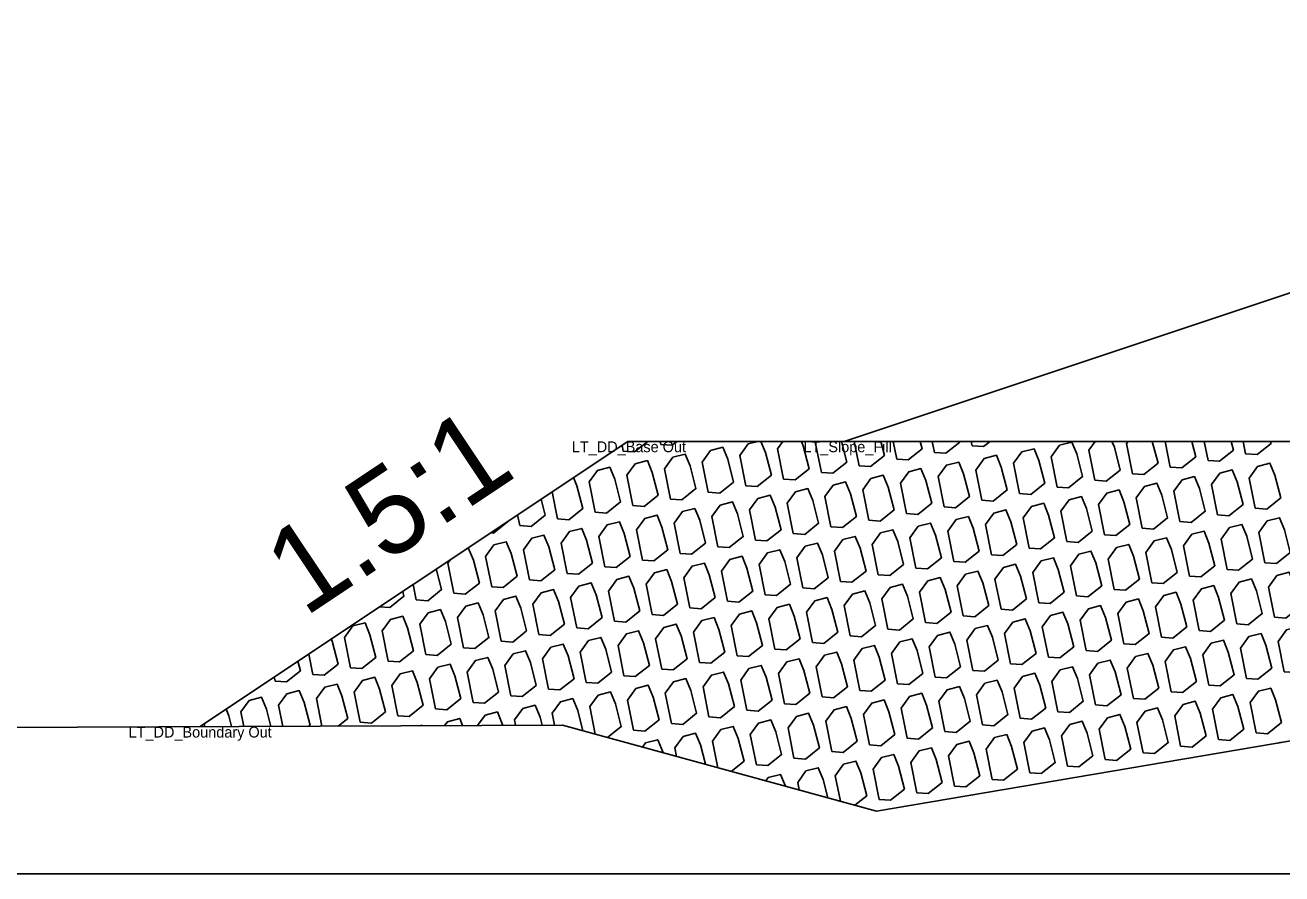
# Model space of a CAD drawing. Extents: x -26 to 203, y -10 to 20020.
# Drawn here: x 60.88 to 72.5, y 17500 to 17507.85 of the extents above; entities that cross this region are included whole.
import ezdxf

# ---------------------------------------------------------------- set-up
doc = ezdxf.new("R2010")
doc.units = 0
for name, color, linetype in [('Default', 7, 'Continuous'), ('Exist Cross Section Cell', 7, 'Continuous'), ('Exist XS Ground Line', 7, 'Continuous'), ('Old_Level_1', 7, 'Continuous'), ('Prop CMT Rip Rap Class II', 7, 'Continuous'), ('Prop CMT Slope Grass', 7, 'Continuous'), ('Prop XS Side Slope Text', 7, 'Continuous')]:
    doc.layers.add(name, color=color, linetype=linetype)

msp = doc.modelspace()

# ---------------------------------------------------------------- linework, layer by layer
at = {"layer": 'Exist Cross Section Cell'}
msp.add_line((0, 17500), (100, 17500), dxfattribs=at)
at = {"layer": 'Exist XS Ground Line'}
for p, q in [((59.91, 17501.349), (65.847, 17501.376)), ((65.847, 17501.376), (68.75, 17500.58)), ((68.75, 17500.58), (73.775, 17501.433))]:
    msp.add_line(p, q, dxfattribs=at)
at = {"layer": 'Old_Level_1'}
for p, q in [((66.397, 17503.965), (66.408, 17503.91)), ((66.751, 17504), (66.757, 17503.972)), ((68.544, 17504), (68.589, 17503.775)), ((68.905, 17504), (68.937, 17503.836)), ((69.266, 17504), (69.286, 17503.898)), ((69.626, 17504), (69.634, 17503.959)), ((71.419, 17504), (71.466, 17503.762)), ((71.78, 17504), (71.815, 17503.824)), ((72.141, 17504), (72.163, 17503.885)), ((65.75, 17503.534), (65.8, 17503.283)), ((65.431, 17503.321), (65.451, 17503.222)), ((64.466, 17502.677), (64.494, 17502.533)), ((63.5, 17502.033), (63.537, 17501.845)), ((63.181, 17501.821), (63.189, 17501.783)), ((62.534, 17501.39), (62.54, 17501.361))]:
    msp.add_line(p, q, dxfattribs=at)
for points in [[(66.408, 17503.91), (66.513, 17503.902), (66.636, 17504)], [(66.757, 17503.972), (66.862, 17503.964), (66.907, 17504)], [(67.654, 17504), (67.564, 17503.977), (67.487, 17503.87), (67.543, 17503.59)], [(67.543, 17503.59), (67.648, 17503.583), (67.778, 17503.686), (67.723, 17503.897), (67.681, 17504)], [(67.885, 17504), (67.836, 17503.932), (67.891, 17503.652)], [(67.891, 17503.652), (67.997, 17503.644), (68.126, 17503.747), (68.072, 17503.958), (68.055, 17504)], [(68.189, 17504), (68.184, 17503.993), (68.24, 17503.713)], [(68.24, 17503.713), (68.345, 17503.706), (68.475, 17503.809), (68.425, 17504)], [(68.589, 17503.775), (68.694, 17503.767), (68.823, 17503.87), (68.79, 17504)], [(68.937, 17503.836), (69.043, 17503.829), (69.172, 17503.932), (69.154, 17504)], [(69.286, 17503.898), (69.391, 17503.89), (69.521, 17503.993), (69.519, 17504)], [(69.634, 17503.959), (69.74, 17503.952), (69.801, 17504)], [(70.072, 17503.517), (70.177, 17503.509), (70.307, 17503.612), (70.252, 17503.823), (70.207, 17503.932), (70.093, 17503.903), (70.016, 17503.797), (70.072, 17503.517)], [(70.421, 17503.578), (70.526, 17503.57), (70.655, 17503.674), (70.601, 17503.884), (70.556, 17503.994), (70.442, 17503.964), (70.365, 17503.858), (70.421, 17503.578)], [(70.772, 17504), (70.714, 17503.92), (70.769, 17503.64)], [(70.769, 17503.64), (70.874, 17503.632), (71.004, 17503.735), (70.949, 17503.946), (70.927, 17504)], [(71.076, 17504), (71.062, 17503.981), (71.118, 17503.701)], [(71.118, 17503.701), (71.223, 17503.693), (71.353, 17503.797), (71.3, 17504)], [(71.466, 17503.762), (71.572, 17503.755), (71.701, 17503.858), (71.664, 17504)], [(71.815, 17503.824), (71.92, 17503.816), (72.05, 17503.919), (72.029, 17504)], [(72.163, 17503.885), (72.269, 17503.878), (72.398, 17503.981), (72.393, 17504)], [(69.723, 17503.455), (69.829, 17503.447), (69.958, 17503.551), (69.904, 17503.761), (69.859, 17503.871), (69.745, 17503.842), (69.668, 17503.735), (69.723, 17503.455)], [(71.555, 17503.258), (71.66, 17503.251), (71.79, 17503.354), (71.736, 17503.565), (71.69, 17503.674), (71.577, 17503.645), (71.5, 17503.538), (71.555, 17503.258)], [(71.904, 17503.32), (72.009, 17503.312), (72.139, 17503.415), (72.084, 17503.626), (72.039, 17503.736), (71.925, 17503.706), (71.848, 17503.6), (71.904, 17503.32)], [(65.8, 17503.283), (65.905, 17503.275), (66.035, 17503.379), (65.98, 17503.589), (65.949, 17503.666)], [(71.207, 17503.197), (71.312, 17503.189), (71.441, 17503.292), (71.387, 17503.503), (71.342, 17503.613), (71.228, 17503.583), (71.151, 17503.477), (71.207, 17503.197)], [(65.451, 17503.222), (65.557, 17503.214), (65.686, 17503.317), (65.648, 17503.465)], [(67.632, 17503.086), (67.737, 17503.079), (67.867, 17503.182), (67.812, 17503.392), (67.767, 17503.502), (67.653, 17503.473), (67.576, 17503.366), (67.632, 17503.086)], [(65.181, 17503.154), (65.208, 17503.152), (65.337, 17503.256), (65.337, 17503.258)], [(64.843, 17502.595), (64.948, 17502.587), (65.078, 17502.69), (65.023, 17502.901), (64.978, 17503.01), (64.957, 17503.005)], [(64.811, 17502.908), (64.787, 17502.875), (64.843, 17502.595)], [(67.023, 17502.459), (67.129, 17502.452), (67.258, 17502.555), (67.204, 17502.765), (67.159, 17502.875), (67.045, 17502.846), (66.968, 17502.739), (67.023, 17502.459)], [(64.494, 17502.533), (64.6, 17502.525), (64.729, 17502.629), (64.68, 17502.82)], [(64.156, 17502.471), (64.251, 17502.464), (64.381, 17502.567), (64.369, 17502.613)], [(63.886, 17501.906), (63.991, 17501.898), (64.121, 17502.002), (64.066, 17502.212), (64.021, 17502.322), (63.908, 17502.293), (63.83, 17502.186), (63.886, 17501.906)], [(63.537, 17501.845), (63.643, 17501.837), (63.772, 17501.94), (63.718, 17502.151), (63.709, 17502.173)], [(66.415, 17501.832), (66.52, 17501.825), (66.65, 17501.928), (66.595, 17502.138), (66.55, 17502.248), (66.437, 17502.219), (66.36, 17502.112), (66.415, 17501.832)], [(63.189, 17501.783), (63.294, 17501.776), (63.424, 17501.879), (63.401, 17501.967)], [(64.672, 17501.525), (64.777, 17501.517), (64.907, 17501.621), (64.852, 17501.831), (64.807, 17501.941), (64.694, 17501.911), (64.617, 17501.805), (64.672, 17501.525)], [(65.021, 17501.586), (65.126, 17501.579), (65.256, 17501.682), (65.201, 17501.893), (65.156, 17502.002), (65.042, 17501.973), (64.965, 17501.866), (65.021, 17501.586)], [(64.324, 17501.463), (64.429, 17501.456), (64.558, 17501.559), (64.504, 17501.77), (64.459, 17501.879), (64.345, 17501.85), (64.268, 17501.743), (64.324, 17501.463)], [(63.501, 17501.365), (63.513, 17501.375), (63.458, 17501.585), (63.413, 17501.695), (63.299, 17501.666), (63.222, 17501.559), (63.261, 17501.364)], [(63.774, 17501.366), (63.861, 17501.436), (63.807, 17501.647), (63.762, 17501.756), (63.648, 17501.727), (63.571, 17501.621), (63.621, 17501.366)], [(66.504, 17501.328), (66.609, 17501.321), (66.739, 17501.424), (66.684, 17501.634), (66.639, 17501.744), (66.525, 17501.715), (66.448, 17501.608), (66.504, 17501.328)], [(69.382, 17501.316), (69.487, 17501.308), (69.616, 17501.411), (69.562, 17501.622), (69.517, 17501.732), (69.403, 17501.702), (69.326, 17501.596), (69.382, 17501.316)], [(69.73, 17501.377), (69.836, 17501.37), (69.965, 17501.473), (69.911, 17501.684), (69.865, 17501.793), (69.752, 17501.764), (69.675, 17501.657), (69.73, 17501.377)], [(72.259, 17501.304), (72.365, 17501.296), (72.494, 17501.399), (72.44, 17501.61), (72.395, 17501.719), (72.281, 17501.69), (72.204, 17501.584), (72.259, 17501.304)], [(63.151, 17501.364), (63.11, 17501.524), (63.064, 17501.633), (62.951, 17501.604), (62.874, 17501.498), (62.9, 17501.362)], [(66.036, 17501.324), (65.987, 17501.511), (65.942, 17501.621), (65.828, 17501.592), (65.751, 17501.485), (65.773, 17501.376)], [(66.264, 17501.262), (66.39, 17501.362), (66.336, 17501.573), (66.291, 17501.683), (66.177, 17501.653), (66.1, 17501.547), (66.15, 17501.293)], [(68.684, 17501.193), (68.79, 17501.185), (68.919, 17501.289), (68.865, 17501.499), (68.82, 17501.609), (68.706, 17501.579), (68.629, 17501.473), (68.684, 17501.193)], [(69.033, 17501.254), (69.138, 17501.247), (69.268, 17501.35), (69.213, 17501.561), (69.168, 17501.67), (69.055, 17501.641), (68.977, 17501.534), (69.033, 17501.254)], [(71.562, 17501.181), (71.667, 17501.173), (71.797, 17501.276), (71.742, 17501.487), (71.697, 17501.596), (71.584, 17501.567), (71.507, 17501.461), (71.562, 17501.181)], [(71.911, 17501.242), (72.016, 17501.234), (72.146, 17501.338), (72.091, 17501.548), (72.046, 17501.658), (71.932, 17501.629), (71.855, 17501.522), (71.911, 17501.242)], [(62.787, 17501.362), (62.761, 17501.462), (62.736, 17501.524)], [(65.294, 17501.373), (65.29, 17501.389), (65.245, 17501.498), (65.131, 17501.469), (65.061, 17501.372)], [(65.658, 17501.375), (65.639, 17501.45), (65.593, 17501.56), (65.48, 17501.53), (65.403, 17501.424), (65.413, 17501.374)], [(67.987, 17501.07), (68.093, 17501.062), (68.222, 17501.166), (68.168, 17501.376), (68.122, 17501.486), (68.009, 17501.456), (67.932, 17501.35), (67.987, 17501.07)], [(68.336, 17501.131), (68.441, 17501.124), (68.571, 17501.227), (68.516, 17501.438), (68.471, 17501.547), (68.357, 17501.518), (68.28, 17501.411), (68.336, 17501.131)], [(70.865, 17501.058), (70.97, 17501.05), (71.1, 17501.153), (71.045, 17501.364), (71, 17501.474), (70.886, 17501.444), (70.809, 17501.338), (70.865, 17501.058)], [(71.214, 17501.119), (71.319, 17501.112), (71.448, 17501.215), (71.394, 17501.425), (71.349, 17501.535), (71.235, 17501.506), (71.158, 17501.399), (71.214, 17501.119)], [(64.55, 17501.37), (64.548, 17501.375), (64.527, 17501.37)], [(64.923, 17501.372), (64.896, 17501.437), (64.782, 17501.407), (64.756, 17501.371)], [(67.407, 17500.948), (67.525, 17501.043), (67.47, 17501.253), (67.425, 17501.363), (67.312, 17501.334), (67.234, 17501.227), (67.283, 17500.982)], [(67.639, 17501.009), (67.744, 17501.001), (67.873, 17501.104), (67.819, 17501.315), (67.774, 17501.424), (67.66, 17501.395), (67.583, 17501.289), (67.639, 17501.009)], [(70.516, 17500.996), (70.622, 17500.989), (70.751, 17501.092), (70.697, 17501.302), (70.652, 17501.412), (70.538, 17501.383), (70.461, 17501.276), (70.516, 17500.996)], [(66.776, 17501.121), (66.773, 17501.13), (66.728, 17501.24), (66.614, 17501.211), (66.587, 17501.173)], [(67.168, 17501.014), (67.122, 17501.192), (67.077, 17501.301), (66.963, 17501.272), (66.886, 17501.166), (66.902, 17501.087)], [(72.484, 17501.214), (72.483, 17501.215), (72.462, 17501.21)], [(68.549, 17500.635), (68.66, 17500.723), (68.605, 17500.934), (68.56, 17501.043), (68.446, 17501.014), (68.369, 17500.907), (68.416, 17500.672)], [(67.908, 17500.811), (67.863, 17500.92), (67.749, 17500.891), (67.727, 17500.861)], [(68.3, 17500.704), (68.257, 17500.872), (68.211, 17500.982), (68.098, 17500.952), (68.021, 17500.846), (68.034, 17500.776)]]:
    msp.add_lwpolyline(points, dxfattribs=at)
for points in [[(67.194, 17503.529), (67.3, 17503.521), (67.429, 17503.624), (67.375, 17503.835), (67.329, 17503.945), (67.216, 17503.915), (67.139, 17503.809)], [(66.497, 17503.406), (66.602, 17503.398), (66.732, 17503.502), (66.677, 17503.712), (66.632, 17503.822), (66.519, 17503.792), (66.441, 17503.686)], [(66.846, 17503.467), (66.951, 17503.46), (67.08, 17503.563), (67.026, 17503.774), (66.981, 17503.883), (66.867, 17503.854), (66.79, 17503.747)], [(69.375, 17503.394), (69.48, 17503.386), (69.61, 17503.489), (69.555, 17503.7), (69.51, 17503.809), (69.396, 17503.78), (69.319, 17503.674)], [(72.252, 17503.381), (72.358, 17503.374), (72.487, 17503.477), (72.433, 17503.687), (72.388, 17503.797), (72.274, 17503.768), (72.197, 17503.661)], [(66.148, 17503.345), (66.254, 17503.337), (66.383, 17503.44), (66.329, 17503.651), (66.284, 17503.76), (66.17, 17503.731), (66.093, 17503.625)], [(68.678, 17503.271), (68.783, 17503.263), (68.912, 17503.366), (68.858, 17503.577), (68.813, 17503.687), (68.699, 17503.657), (68.622, 17503.551)], [(69.026, 17503.332), (69.131, 17503.325), (69.261, 17503.428), (69.206, 17503.638), (69.161, 17503.748), (69.048, 17503.719), (68.971, 17503.612)], [(67.98, 17503.148), (68.086, 17503.14), (68.215, 17503.243), (68.161, 17503.454), (68.116, 17503.564), (68.002, 17503.534), (67.925, 17503.428)], [(68.329, 17503.209), (68.434, 17503.202), (68.564, 17503.305), (68.509, 17503.515), (68.464, 17503.625), (68.35, 17503.596), (68.273, 17503.489)], [(70.858, 17503.135), (70.963, 17503.128), (71.093, 17503.231), (71.038, 17503.442), (70.993, 17503.551), (70.879, 17503.522), (70.802, 17503.415)], [(67.283, 17503.025), (67.388, 17503.017), (67.518, 17503.12), (67.464, 17503.331), (67.418, 17503.441), (67.305, 17503.411), (67.228, 17503.305)], [(70.509, 17503.074), (70.615, 17503.066), (70.744, 17503.17), (70.69, 17503.38), (70.645, 17503.49), (70.531, 17503.46), (70.454, 17503.354)], [(66.935, 17502.963), (67.04, 17502.956), (67.169, 17503.059), (67.115, 17503.27), (67.07, 17503.379), (66.956, 17503.35), (66.879, 17503.243)], [(69.812, 17502.951), (69.917, 17502.943), (70.047, 17503.047), (69.993, 17503.257), (69.947, 17503.367), (69.834, 17503.337), (69.757, 17503.231)], [(70.161, 17503.013), (70.266, 17503.005), (70.396, 17503.108), (70.341, 17503.319), (70.296, 17503.428), (70.182, 17503.399), (70.105, 17503.293)], [(66.237, 17502.84), (66.343, 17502.833), (66.472, 17502.936), (66.418, 17503.147), (66.373, 17503.256), (66.259, 17503.227), (66.182, 17503.12)], [(66.586, 17502.902), (66.691, 17502.894), (66.821, 17502.997), (66.766, 17503.208), (66.721, 17503.318), (66.607, 17503.288), (66.53, 17503.182)], [(69.115, 17502.828), (69.22, 17502.82), (69.35, 17502.924), (69.295, 17503.134), (69.25, 17503.244), (69.136, 17503.215), (69.059, 17503.108)], [(69.464, 17502.89), (69.569, 17502.882), (69.698, 17502.985), (69.644, 17503.196), (69.599, 17503.305), (69.485, 17503.276), (69.408, 17503.17)], [(71.993, 17502.816), (72.098, 17502.808), (72.227, 17502.911), (72.173, 17503.122), (72.128, 17503.232), (72.014, 17503.202), (71.937, 17503.096)], [(72.341, 17502.877), (72.447, 17502.87), (72.576, 17502.973), (72.522, 17503.183), (72.476, 17503.293), (72.363, 17503.264), (72.286, 17503.157)], [(65.54, 17502.718), (65.645, 17502.71), (65.775, 17502.813), (65.721, 17503.024), (65.675, 17503.133), (65.562, 17503.104), (65.485, 17502.997)], [(65.889, 17502.779), (65.994, 17502.771), (66.124, 17502.875), (66.069, 17503.085), (66.024, 17503.195), (65.91, 17503.165), (65.833, 17503.059)], [(68.418, 17502.705), (68.523, 17502.698), (68.653, 17502.801), (68.598, 17503.011), (68.553, 17503.121), (68.439, 17503.092), (68.362, 17502.985)], [(68.766, 17502.767), (68.872, 17502.759), (69.001, 17502.862), (68.947, 17503.073), (68.902, 17503.182), (68.788, 17503.153), (68.711, 17503.047)], [(71.295, 17502.693), (71.401, 17502.685), (71.53, 17502.788), (71.476, 17502.999), (71.431, 17503.109), (71.317, 17503.079), (71.24, 17502.973)], [(71.644, 17502.754), (71.749, 17502.747), (71.879, 17502.85), (71.824, 17503.06), (71.779, 17503.17), (71.666, 17503.141), (71.588, 17503.034)], [(65.192, 17502.656), (65.297, 17502.648), (65.426, 17502.752), (65.372, 17502.962), (65.327, 17503.072), (65.213, 17503.042), (65.136, 17502.936)], [(67.721, 17502.582), (67.826, 17502.575), (67.955, 17502.678), (67.901, 17502.888), (67.856, 17502.998), (67.742, 17502.969), (67.665, 17502.862)], [(68.069, 17502.644), (68.174, 17502.636), (68.304, 17502.739), (68.25, 17502.95), (68.204, 17503.06), (68.091, 17503.03), (68.014, 17502.924)], [(70.598, 17502.57), (70.704, 17502.562), (70.833, 17502.665), (70.779, 17502.876), (70.733, 17502.986), (70.62, 17502.956), (70.543, 17502.85)], [(70.947, 17502.631), (71.052, 17502.624), (71.182, 17502.727), (71.127, 17502.938), (71.082, 17503.047), (70.968, 17503.018), (70.891, 17502.911)], [(67.372, 17502.521), (67.477, 17502.513), (67.607, 17502.616), (67.552, 17502.827), (67.507, 17502.937), (67.393, 17502.907), (67.316, 17502.801)], [(69.901, 17502.447), (70.006, 17502.439), (70.136, 17502.543), (70.081, 17502.753), (70.036, 17502.863), (69.923, 17502.833), (69.845, 17502.727)], [(70.25, 17502.508), (70.355, 17502.501), (70.484, 17502.604), (70.43, 17502.815), (70.385, 17502.924), (70.271, 17502.895), (70.194, 17502.788)], [(66.326, 17502.336), (66.432, 17502.329), (66.561, 17502.432), (66.507, 17502.643), (66.461, 17502.752), (66.348, 17502.723), (66.271, 17502.616)], [(66.675, 17502.398), (66.78, 17502.39), (66.91, 17502.493), (66.855, 17502.704), (66.81, 17502.814), (66.696, 17502.784), (66.619, 17502.678)], [(69.204, 17502.324), (69.309, 17502.316), (69.439, 17502.42), (69.384, 17502.63), (69.339, 17502.74), (69.225, 17502.71), (69.148, 17502.604)], [(69.552, 17502.386), (69.658, 17502.378), (69.787, 17502.481), (69.733, 17502.692), (69.688, 17502.801), (69.574, 17502.772), (69.497, 17502.665)], [(72.43, 17502.373), (72.535, 17502.366), (72.665, 17502.469), (72.611, 17502.679), (72.565, 17502.789), (72.452, 17502.76), (72.375, 17502.653)], [(65.629, 17502.213), (65.734, 17502.206), (65.864, 17502.309), (65.809, 17502.52), (65.764, 17502.629), (65.65, 17502.6), (65.573, 17502.493)], [(65.978, 17502.275), (66.083, 17502.267), (66.212, 17502.37), (66.158, 17502.581), (66.113, 17502.691), (65.999, 17502.661), (65.922, 17502.555)], [(68.855, 17502.263), (68.961, 17502.255), (69.09, 17502.358), (69.036, 17502.569), (68.991, 17502.678), (68.877, 17502.649), (68.8, 17502.543)], [(71.733, 17502.25), (71.838, 17502.243), (71.968, 17502.346), (71.913, 17502.556), (71.868, 17502.666), (71.754, 17502.637), (71.677, 17502.53)], [(72.082, 17502.312), (72.187, 17502.304), (72.316, 17502.407), (72.262, 17502.618), (72.217, 17502.728), (72.103, 17502.698), (72.026, 17502.592)], [(64.932, 17502.091), (65.037, 17502.083), (65.167, 17502.186), (65.112, 17502.397), (65.067, 17502.506), (64.953, 17502.477), (64.876, 17502.37)], [(65.28, 17502.152), (65.386, 17502.144), (65.515, 17502.248), (65.461, 17502.458), (65.416, 17502.568), (65.302, 17502.538), (65.225, 17502.432)], [(68.158, 17502.14), (68.263, 17502.132), (68.393, 17502.235), (68.338, 17502.446), (68.293, 17502.555), (68.18, 17502.526), (68.102, 17502.42)], [(68.507, 17502.201), (68.612, 17502.193), (68.742, 17502.297), (68.687, 17502.507), (68.642, 17502.617), (68.528, 17502.588), (68.451, 17502.481)], [(71.036, 17502.127), (71.141, 17502.12), (71.271, 17502.223), (71.216, 17502.433), (71.171, 17502.543), (71.057, 17502.514), (70.98, 17502.407)], [(71.384, 17502.189), (71.49, 17502.181), (71.619, 17502.284), (71.565, 17502.495), (71.52, 17502.605), (71.406, 17502.575), (71.329, 17502.469)], [(64.583, 17502.029), (64.689, 17502.021), (64.818, 17502.125), (64.764, 17502.335), (64.718, 17502.445), (64.605, 17502.415), (64.528, 17502.309)], [(67.461, 17502.017), (67.566, 17502.009), (67.696, 17502.112), (67.641, 17502.323), (67.596, 17502.433), (67.482, 17502.403), (67.405, 17502.297)], [(67.81, 17502.078), (67.915, 17502.071), (68.044, 17502.174), (67.99, 17502.384), (67.945, 17502.494), (67.831, 17502.465), (67.754, 17502.358)], [(70.339, 17502.004), (70.444, 17501.997), (70.573, 17502.1), (70.519, 17502.311), (70.474, 17502.42), (70.36, 17502.391), (70.283, 17502.284)], [(70.687, 17502.066), (70.792, 17502.058), (70.922, 17502.161), (70.868, 17502.372), (70.822, 17502.482), (70.709, 17502.452), (70.632, 17502.346)], [(64.235, 17501.968), (64.34, 17501.96), (64.469, 17502.063), (64.415, 17502.274), (64.37, 17502.383), (64.256, 17502.354), (64.179, 17502.248)], [(66.764, 17501.894), (66.869, 17501.886), (66.999, 17501.989), (66.944, 17502.2), (66.899, 17502.31), (66.785, 17502.28), (66.708, 17502.174)], [(67.112, 17501.955), (67.218, 17501.948), (67.347, 17502.051), (67.293, 17502.261), (67.248, 17502.371), (67.134, 17502.342), (67.057, 17502.235)], [(69.641, 17501.881), (69.747, 17501.874), (69.876, 17501.977), (69.822, 17502.188), (69.777, 17502.297), (69.663, 17502.268), (69.586, 17502.161)], [(69.99, 17501.943), (70.095, 17501.935), (70.225, 17502.038), (70.17, 17502.249), (70.125, 17502.359), (70.011, 17502.329), (69.934, 17502.223)], [(72.519, 17501.869), (72.624, 17501.861), (72.754, 17501.965), (72.699, 17502.175), (72.654, 17502.285), (72.54, 17502.256), (72.463, 17502.149)], [(66.067, 17501.771), (66.172, 17501.763), (66.301, 17501.866), (66.247, 17502.077), (66.202, 17502.187), (66.088, 17502.157), (66.011, 17502.051)], [(68.944, 17501.759), (69.049, 17501.751), (69.179, 17501.854), (69.125, 17502.065), (69.079, 17502.174), (68.966, 17502.145), (68.889, 17502.038)], [(69.293, 17501.82), (69.398, 17501.812), (69.528, 17501.916), (69.473, 17502.126), (69.428, 17502.236), (69.314, 17502.206), (69.237, 17502.1)], [(71.822, 17501.746), (71.927, 17501.739), (72.057, 17501.842), (72.002, 17502.052), (71.957, 17502.162), (71.843, 17502.133), (71.766, 17502.026)], [(72.17, 17501.808), (72.276, 17501.8), (72.405, 17501.903), (72.351, 17502.114), (72.306, 17502.223), (72.192, 17502.194), (72.115, 17502.088)], [(65.369, 17501.648), (65.475, 17501.64), (65.604, 17501.743), (65.55, 17501.954), (65.505, 17502.064), (65.391, 17502.034), (65.314, 17501.928)], [(65.718, 17501.709), (65.823, 17501.702), (65.953, 17501.805), (65.898, 17502.016), (65.853, 17502.125), (65.739, 17502.096), (65.662, 17501.989)], [(68.247, 17501.636), (68.352, 17501.628), (68.482, 17501.731), (68.427, 17501.942), (68.382, 17502.051), (68.268, 17502.022), (68.191, 17501.916)], [(68.596, 17501.697), (68.701, 17501.689), (68.83, 17501.793), (68.776, 17502.003), (68.731, 17502.113), (68.617, 17502.083), (68.54, 17501.977)], [(71.473, 17501.685), (71.578, 17501.677), (71.708, 17501.78), (71.654, 17501.991), (71.608, 17502.101), (71.495, 17502.071), (71.418, 17501.965)], [(67.55, 17501.513), (67.655, 17501.505), (67.785, 17501.608), (67.73, 17501.819), (67.685, 17501.928), (67.571, 17501.899), (67.494, 17501.793)], [(67.898, 17501.574), (68.004, 17501.566), (68.133, 17501.67), (68.079, 17501.88), (68.034, 17501.99), (67.92, 17501.961), (67.843, 17501.854)], [(70.776, 17501.562), (70.881, 17501.554), (71.011, 17501.657), (70.956, 17501.868), (70.911, 17501.978), (70.797, 17501.948), (70.72, 17501.842)], [(71.125, 17501.623), (71.23, 17501.616), (71.359, 17501.719), (71.305, 17501.929), (71.26, 17502.039), (71.146, 17502.01), (71.069, 17501.903)], [(63.975, 17501.402), (64.08, 17501.394), (64.21, 17501.498), (64.155, 17501.708), (64.11, 17501.818), (63.996, 17501.788), (63.919, 17501.682)], [(67.201, 17501.451), (67.306, 17501.444), (67.436, 17501.547), (67.382, 17501.757), (67.336, 17501.867), (67.223, 17501.838), (67.146, 17501.731)], [(70.079, 17501.439), (70.184, 17501.431), (70.314, 17501.534), (70.259, 17501.745), (70.214, 17501.855), (70.1, 17501.825), (70.023, 17501.719)], [(70.427, 17501.5), (70.533, 17501.493), (70.662, 17501.596), (70.608, 17501.806), (70.563, 17501.916), (70.449, 17501.887), (70.372, 17501.78)], [(66.853, 17501.39), (66.958, 17501.382), (67.087, 17501.485), (67.033, 17501.696), (66.988, 17501.806), (66.874, 17501.776), (66.797, 17501.67)], [(70.168, 17500.935), (70.273, 17500.927), (70.403, 17501.03), (70.348, 17501.241), (70.303, 17501.351), (70.189, 17501.321), (70.112, 17501.215)], [(69.471, 17500.812), (69.576, 17500.804), (69.705, 17500.907), (69.651, 17501.118), (69.606, 17501.228), (69.492, 17501.198), (69.415, 17501.092)], [(69.819, 17500.873), (69.924, 17500.866), (70.054, 17500.969), (69.999, 17501.179), (69.954, 17501.289), (69.841, 17501.26), (69.764, 17501.153)], [(69.122, 17500.75), (69.227, 17500.743), (69.357, 17500.846), (69.302, 17501.057), (69.257, 17501.166), (69.143, 17501.137), (69.066, 17501.03)], [(68.773, 17500.689), (68.879, 17500.681), (69.008, 17500.784), (68.954, 17500.995), (68.909, 17501.105), (68.795, 17501.075), (68.718, 17500.969)]]:
    msp.add_lwpolyline(points, close=True, dxfattribs=at)
at = {"layer": 'Prop CMT Rip Rap Class II'}
msp.add_lwpolyline([(79.309, 17504), (66.45, 17504), (62.491, 17501.361)], dxfattribs=at)
at = {"layer": 'Prop CMT Slope Grass'}
msp.add_lwpolyline([(80, 17507.85), (68.45, 17504)], dxfattribs=at)

# ---------------------------------------------------------------- texts
at = {"layer": 'Default'}
for s, p in [('LT_DD_Base Out', (65.933, 17503.9)), ('LT_Slope_Fill', (68.074, 17503.9)), ('LT_DD_Boundary Out', (61.835, 17501.261))]:
    msp.add_text(s, height=0.1, dxfattribs=at).set_placement(p)
at = {"layer": 'Prop XS Side Slope Text'}
msp.add_text('1.5:1', height=0.8, rotation=33.6914, dxfattribs=at).set_placement((63.461, 17502.368))

doc.saveas('drawing.dxf')
